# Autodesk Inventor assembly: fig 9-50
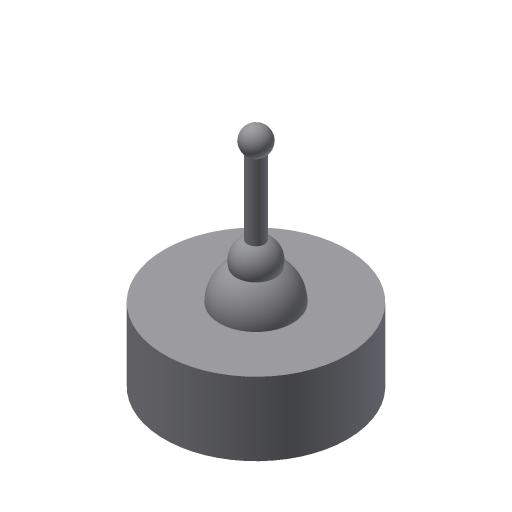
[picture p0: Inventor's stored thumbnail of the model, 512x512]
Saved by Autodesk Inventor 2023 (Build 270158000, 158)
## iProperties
Created: 2013-07
Part Number: fig 9-50
Document SubType Name: Assembly
Designer: CADCIM
Author: CADCIM
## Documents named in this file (3)
- D:\PROJECTS\Project 2022\Autodesk Inventor For Professional 2023\RESOURCES INVENTOR 2023\RESOURCES INVENTOR 2023\Inventor_2023_Part\Inventor_2023_Part\c09_Inv_2023_prt\fig 9-51.iam
- D:\PROJECTS\Project 2022\Autodesk Inventor For Professional 2023\RESOURCES INVENTOR 2023\RESOURCES INVENTOR 2023\Inventor_2023_Part\Inventor_2023_Part\c09_Inv_2023_prt\19.ipt
- D:\PROJECTS\Project 2022\Autodesk Inventor For Professional 2023\RESOURCES INVENTOR 2023\RESOURCES INVENTOR 2023\Inventor_2023_Part\Inventor_2023_Part\c09_Inv_2023_prt\20.ipt
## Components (2 placed, 2 different names)
1. 19:1 — Ball:1
2. 20:1 — Ball:1
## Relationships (1: BallJoint 1)
- Ball:1: 19:1 ↔ 20:1
